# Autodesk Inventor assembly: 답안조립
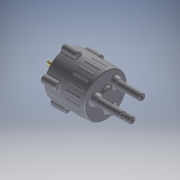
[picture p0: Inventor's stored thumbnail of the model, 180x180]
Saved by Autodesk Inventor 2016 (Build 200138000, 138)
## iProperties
Created: 2015-11
Part Number: 답안조립
Material: 일반
Document SubType Name: Assembly
Designer: eco
Author: eco
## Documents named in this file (14)
- C:\Users\eco\Desktop\1급\Inventor1급-하의숙\답안조립품.iam
- C:\Users\eco\Desktop\1급\Inventor1급-하의숙\1급\공용부품_20151104_1\본체.ipt
- C:\Users\eco\Desktop\1급\Inventor1급-하의숙\1급\공용부품_20151104_1\커버.ipt
- C:\Users\eco\Desktop\1급\Inventor1급-하의숙\1급\공용부품_20151104_1\판캠.ipt
- C:\Users\eco\Desktop\1급\Inventor1급-하의숙\1급\공용부품_20151104_1\메인 축.ipt
- C:\Users\eco\Desktop\1급\Inventor1급-하의숙\1급\공용부품_20151104_1\멈춤링 10 x 1.ipt
- C:\Users\eco\Desktop\1급\Inventor1급-하의숙\1급\공용부품_20151104_1\멈춤링 22 x 1.2.ipt
- C:\Users\eco\Desktop\1급\Inventor1급-하의숙\1급\공용부품_20151104_1\슬라이드 축.ipt
- C:\Users\eco\Desktop\1급\Inventor1급-하의숙\1급\공용부품_20151104_1\베어링 NA 4900.ipt
- C:\Users\eco\Desktop\1급\Inventor1급-하의숙\1급\공용부품_20151104_1\오일실.ipt
- C:\Users\eco\Desktop\1급\Inventor1급-하의숙\1급\공용부품_20151104_1\M5x0.8x20.ipt
- C:\Users\eco\Desktop\1급\Inventor1급-하의숙\가변스프링01.ipt
- C:\Users\eco\Desktop\1급\Inventor1급-하의숙\가변스프링02.ipt
- C:\Users\eco\Desktop\1급\Inventor1급-하의숙\가변스프링03.ipt
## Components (8 placed, 4 different names)
1. 가변스프링01:1
2. 가변스프링02:1
3. 가변스프링03:1
4. M5x0.8x20:1
5. M5x0.8x20:2
6. M5x0.8x20:3
7. M5x0.8x20:4
8. M5x0.8x20:5
